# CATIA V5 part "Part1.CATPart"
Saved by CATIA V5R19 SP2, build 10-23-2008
Part number: squelette bati
Publications: "royontubebati", "Plan zx", "Point.14"
Bounding box of the stored display mesh (mm): x -54 to 54, y -72 to 50.4, z -9 to 60
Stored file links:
  F:\Travaux\Modélisations\CFAO_2011\CFAO_2011_MMS\CFAO_2011_MMS_DONE\CFAO_2011_MMS_jboiteux\Catia\Part1.CATPart
  C:\catia thinkmotion\Nouveau dossier (2)\part5.CATPart
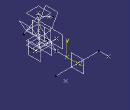
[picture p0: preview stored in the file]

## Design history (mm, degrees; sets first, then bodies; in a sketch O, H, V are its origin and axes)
Parameters
  royontubebati = 9 mm
Body1 (main body)
  Point1: (0, 0, 0)
  Line1: type Normal, RefPoint Point1, RefSkin zx-plane, Start 0, End 26.4 {= royontubebati *44/15}
  Point2: (0, 0, 0), relative to vertex of Line1
  Line2: type Normal, RefPoint Point2, RefSkin yz-plane, Start -54, End 54 {= royontubebati *6}
  Line3: type Normal, RefPoint vertex of Line2, RefSkin zx-plane, Start 0, End 24 {= royontubebati *8/3}
  Line4: type Normal, RefPoint vertex of Line2, RefSkin zx-plane, Start 0, End 24 {= royontubebati *8/3}
  Point3: (0, 0, 0), relative to vertex of Line3
  Point4: (0, 0, 0), relative to vertex of Line4
  Line5: type Normal, RefPoint Point1, RefSkin zx-plane, Start 0, End -72 {= -royontubebati *8}
  Point5: (0, 0, 0), relative to vertex of Line5
  Line6: type Normal, RefPoint Point5, RefSkin xy-plane, Start 0, End -9 {= -royontubebati}
  Point6: (0, 0, 0), relative to vertex of Line6
  Line7: type PtDir, RefPoint Point6, Direction yz-plane, Start 20, End -20
  Line8: type Normal, RefPoint Point5, RefSkin xy-plane, Start 0, End 60 {= royontubebati *20/3}
  Point7: type OnCurve, Support Line5, Length 18 {= royontubebati *2}
  Point8: type OnCurve, Support Line5, Length 45 {= royontubebati *5}
  Point9: type OnCurve, Support Line8, Length 21.6 {= royontubebati *12/5}
  Point10: (0, 0, 0), relative to vertex of Line8
  Point11: type OnCurve, Support Line8, Length 36 {= royontubebati *4}
  Line9: type PtPt, FirstPoint Point11, SecondPoint Point8
  Line10: type Normal, RefPoint Point7, RefSkin yz-plane, Start -27.6, End 27.6 {= royontubebati *46/15}
  Plane1: type Normal, Curve Line8, RefPoint Point9
  Point12: type OnCurve, Support Line8, Length 6 {= royontubebati *2/3}
  Plane2: stored without definition
  Line11: type Angle, RefPoint Point12, Curve Line8, Support Plane2, Start 0, End -42.3 {= -royontubebati*4.7}, Angle 60
  Plane3: stored without definition
  Line12: type Angle, RefPoint Point12, Curve Line8, Support Plane3, Start 0, End -42.3 {= -royontubebati*4.7}, Angle -60
  Point13: type OnCurve, Support Line11, Length 29.7 {= royontubebati *3.3}
  Point14: type OnCurve, Support Line12, Length 29.7 {= royontubebati *3.3}
  Plane4: type Normal, Curve Line12, RefPoint Point14
  Plane5: type Normal, Curve Line11, RefPoint Point13
  Line13: stored without definition
  Point15: stored without definition
  Line14: stored without definition
  Point16: stored without definition
  Line15: stored without definition
  Plane6: type OffsetPt, RefPlane yz-plane, RefPoint Point2
  Plane7: type OffsetPt, RefPlane xy-plane, RefPoint Point5
  Plane8: type OffsetPt, RefPlane xy-plane, RefPoint Point10
  Plane9: type OffsetPt, RefPlane xy-plane, RefPoint Point6
  Plane10: type OffsetPt, RefPlane yz-plane, RefPoint Point9
  Plane11: type OffsetPt, RefPlane yz-plane, RefPoint Point7
  Sketch1 on Plane6, origin (0, 0, 0), H (0, 1, 0), V (0, 0, 1)
    circle A1 centre (28.9731, 36.0773) radius 0
    point P1 (28.9731, 36.0773)
    coincidence: A1 P1
  Point17: (0, 0, 0), relative to vertex of Line10
  Point18: (0, 0, 0), relative to vertex of Line10
  Plane12: type OffsetPt, RefPlane Plane11, RefPoint Point17
  Plane13: type OffsetPt, RefPlane Plane11, RefPoint Point18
